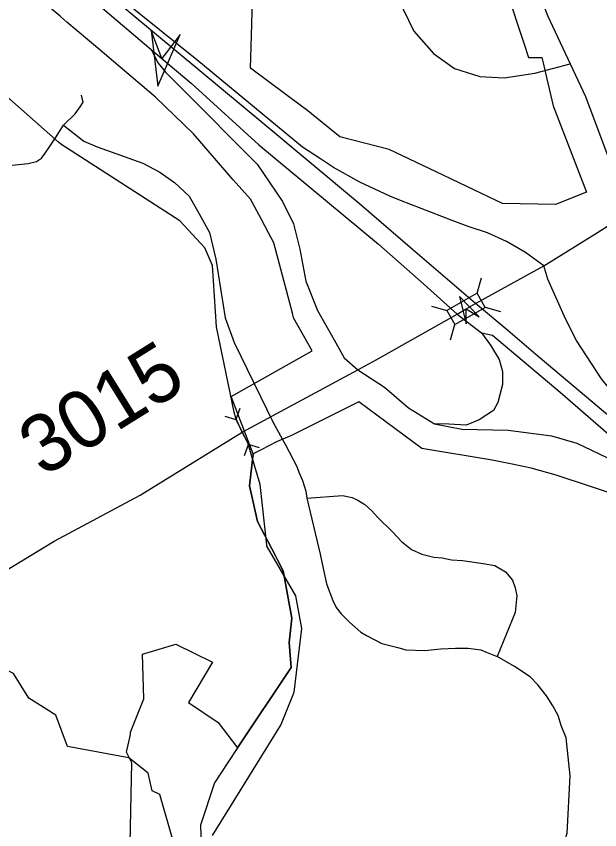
# Model space of a CAD drawing. Extents: x 2001466 to 31450019, y -30647475 to 847247.
# Drawn here: x 31439706 to 31442235, y -30624939 to -30621416 of the extents above; entities that cross this region are included whole.
import ezdxf

# ---------------------------------------------------------------- set-up
doc = ezdxf.new("R2010")
doc.units = 0
for name, color, linetype in [('Exist Boundary Political City Limit New', 7, 'Continuous'), ('Exist Hydrographic Creek Single Shore', 7, 'Continuous'), ('Exist Road Non-System Type 51', 7, 'Continuous'), ('Exist Road Primary Interstate Divided Center Attributed', 7, 'Continuous'), ('Exist Road Primary Interstate Ramp 1 Lane Attributed', 7, 'Continuous'), ('Exist Road Primary Interstate Structure Ovrhead Sign Attributed CELL', 7, 'Continuous'), ('Exist Road Secondary Structure Culvert CELL', 7, 'Continuous'), ('Exist Road Secondary Structure Standard Bridge Attributed CELL', 7, 'Continuous'), ('Exist Road Secondary Structure Standard Bridge CELL', 7, 'Continuous'), ('Exist Road Secondary Type 51 Attributed', 7, 'Continuous'), ('Exist Road Secondary Type 51 Number Label', 7, 'Continuous'), ('Map Preparation Boundary City Limit Buffer Line', 7, 'Continuous')]:
    doc.layers.add(name, color=color, linetype=linetype)

msp = doc.modelspace()

# ---------------------------------------------------------------- linework, layer by layer
at = {"layer": 'Exist Boundary Political City Limit New'}
for points in [[(31441833.9, -30621313.3), (31441905.3, -30621529), (31441926.8, -30621594.3), (31441983.8, -30621594.5), (31441989.4, -30621618.3), (31442004, -30621681.1), (31442033, -30621804.8), (31442177.8, -30622178.8), (31442042.9, -30622232.2), (31441814, -30622227.6), (31441691.6, -30622169.4), (31441525.9, -30622090.5), (31441321.9, -30621993.3), (31441108.8, -30621939), (31440961.9, -30621820), (31440948.3, -30621809.8), (31440720.8, -30621641.5), (31440723.5, -30621548.6), (31440735.3, -30621147.8)], [(31442352.3, -30623504.6), (31442046.3, -30623403.6), (31441938.3, -30623373.6), (31441854.9, -30623356.6), (31441768.4, -30623338.8), (31441463.8, -30623288.1), (31441191.6, -30623086.7), (31440898.5, -30623231.4), (31440834.5, -30623260), (31440767.8, -30623294.1), (31440732.9, -30623312)], [(31440732.9, -30623312), (31440716.4, -30623450.1), (31440751.9, -30623605.1), (31440829.4, -30623753.3), (31440838.1, -30623770.1), (31440863.1, -30623817.8), (31440900.4, -30624023.5), (31440888.8, -30624128.8), (31440897.3, -30624237.5), (31440664.3, -30624584.6)], [(31440664.3, -30624584.6), (31440622.6, -30624648.1), (31440564.8, -30624737), (31440504.1, -30624919.1), (31440518.3, -30625317.9), (31440493, -30625317.1), (31440483.9, -30625317), (31440193.6, -30625312.4)]]:
    msp.add_lwpolyline(points, dxfattribs=at)
at = {"layer": 'Exist Hydrographic Creek Single Shore'}
for p, q in [((31440791.7, -30623705.4), (31440763.8, -30623444.3)), ((31440907.2, -30624351.4), (31440909.5, -30624345.8))]:
    msp.add_line(p, q, dxfattribs=at)
for points in [[(31439888.4, -30621961.3), (31439539.5, -30621654.5), (31439388.3, -30621448), (31438996.5, -30621246.3), (31438888.4, -30621129.3), (31438779.3, -30620940), (31438746.5, -30620821.2), (31438753.5, -30620214.4), (31438794.3, -30620077.4)], [(31440763.8, -30623444.3), (31440709.3, -30623263.2), (31440685, -30623217.3), (31440658.4, -30623156.7), (31440651, -30623131.2), (31440574.4, -30622761.7), (31440557.3, -30622495.6), (31440523.5, -30622419.4), (31440415.4, -30622302.4), (31439898.5, -30621970.2), (31439888.4, -30621961.3)], [(31440512.4, -30625135.9), (31440412.4, -30625078), (31440328.5, -30624787.5), (31440294.5, -30624770.5), (31440277.4, -30624694.7), (31440194.4, -30624627.4), (31439927.4, -30624579.3), (31439877.4, -30624443.7), (31439760.5, -30624369.1), (31439693.5, -30624262.8), (31439260.4, -30624053.8), (31438998.6, -30623756.5), (31438963.5, -30623729.3), (31438939.7, -30623703.8), (31438905.2, -30623679.5), (31438856.5, -30623647.7), (31438567.5, -30623465.4), (31438475.4, -30623365.1)], [(31440805.3, -30623733.3), (31440792.3, -30623711.1), (31440791.7, -30623705.4)], [(31440909.5, -30624345.8), (31440910.4, -30624343.5), (31440943.4, -30624068.5), (31440918.4, -30623926.9), (31440805.3, -30623733.3)], [(31440556.4, -30624964.6), (31440852.4, -30624486.6), (31440907.2, -30624351.4)]]:
    msp.add_lwpolyline(points, dxfattribs=at)
at = {"layer": 'Exist Road Non-System Type 51'}
for p, q in [((31439875.5, -30621943), (31439911.2, -30621888)), ((31440820.9, -30623178.6), (31440872.6, -30623272.2))]:
    msp.add_line(p, q, dxfattribs=at)
for points in [[(31441344.4, -30621128.1), (31441361.8, -30621294.2), (31441383, -30621385), (31441429.3, -30621481.6), (31441514.3, -30621578.2), (31441605, -30621641.9), (31441715, -30621676.7), (31441821.2, -30621682.5), (31441954.4, -30621663.2), (31442107.5, -30621621.9)], [(31439911.2, -30621888), (31439960.7, -30621838.5), (31439982.7, -30621808.2), (31439996.5, -30621788.9), (31439988.2, -30621758.7)], [(31439911.2, -30621888), (31439998.7, -30621956.8), (31440056.4, -30621981.6), (31440254.4, -30622053.1), (31440328.6, -30622091.6), (31440391.9, -30622135.7), (31440455.1, -30622196.2), (31440490.9, -30622259.5), (31440543.1, -30622353.1), (31440570.6, -30622468.6), (31440611.9, -30622721.8), (31440650.4, -30622829.1), (31440820.9, -30623178.6)], [(31439688.5, -30622061.4), (31439757.3, -30622053.5), (31439793.1, -30622044.7), (31439815, -30622030.2), (31439831.5, -30622009.1), (31439850.7, -30621981.6), (31439875.5, -30621943)], [(31440872.6, -30623272.2), (31440922.1, -30623365.7), (31440930.3, -30623390.5), (31440946.8, -30623426.3), (31440960.6, -30623473), (31440966.1, -30623503.3)], [(31440966.1, -30623503.3), (31441120.1, -30623492.3), (31441161.3, -30623500.6), (31441186.1, -30623511.6), (31441216.3, -30623530.8), (31441246.6, -30623558.3), (31441271.3, -30623585.9), (31441337.3, -30623649.1), (31441375.8, -30623690.4), (31441419.8, -30623726.2), (31441463.8, -30623745.5), (31441516, -30623759.2), (31441551.8, -30623762), (31441593, -30623770.2), (31441639.8, -30623773), (31441730.5, -30623786.7), (31441780, -30623795), (31441826.8, -30623822.5), (31441857, -30623858.3), (31441868, -30623891.3), (31441876.3, -30623927.1), (31441868, -30623998.6), (31441791, -30624188.5)], [(31440966.1, -30623503.3), (31441023.8, -30623745.5), (31441050.8, -30623874.8), (31441078.3, -30623946.3), (31441092, -30623976.6), (31441114, -30624004.1), (31441149.8, -30624039.9), (31441199.3, -30624083.9), (31441224, -30624097.7), (31441259.8, -30624117), (31441290, -30624133.5), (31441325.8, -30624141.7), (31441359.3, -30624150), (31441395, -30624161), (31441477.5, -30624163.7), (31441546.3, -30624155.5), (31441609.5, -30624152.7), (31441664.5, -30624152.7), (31441719.5, -30624161), (31441747, -30624172), (31441791, -30624188.5)], [(31441646.7, -30627115.6), (31441742.3, -30627044.7), (31441976.6, -30626829.8), (31442132.8, -30626673.5), (31442152.3, -30626399.9), (31442113.3, -30625970.1), (31442015.7, -30625423), (31441996.1, -30625266.7), (31442093.8, -30624954.1), (31442106.7, -30624705.8), (31442090.2, -30624540.7), (31442068.2, -30624488.4), (31442054.5, -30624444.4), (31442032.5, -30624403.1), (31442005, -30624359.1), (31441966.5, -30624312.3), (31441933.5, -30624276.6), (31441865.3, -30624232.5), (31441791, -30624188.5)]]:
    msp.add_lwpolyline(points, dxfattribs=at)
at = {"layer": 'Exist Road Primary Interstate Divided Center Attributed'}
for points in [[(31438048.9, -30619684.1), (31438111.1, -30619738.8), (31438627.8, -30620173.3), (31438916.5, -30620414.6), (31439590.6, -30620971.6), (31439878.6, -30621209.9), (31440291.2, -30621559.8)], [(31441697.1, -30622660.9), (31441423.5, -30622426.6), (31441193.4, -30622228.5), (31440775, -30621879.5), (31440032.5, -30621260.9)], [(31440291.2, -30621559.8), (31440337.5, -30621598.9), (31440464.4, -30621706.8), (31440757.3, -30621972.5), (31441275.5, -30622403.3), (31441473.2, -30622576.6), (31441616.7, -30622706)], [(31442906.5, -30623678.1), (31442625.9, -30623443.3), (31442279, -30623151), (31441958.6, -30622881.2), (31441836.5, -30622777.1), (31441697.1, -30622660.9)], [(31441616.7, -30622706), (31441722.9, -30622788.1)], [(31441722.9, -30622788.1), (31441770.5, -30622798), (31442064, -30623044.1), (31442448.1, -30623377.7), (31442660.8, -30623560.6)]]:
    msp.add_lwpolyline(points, dxfattribs=at)
at = {"layer": 'Exist Road Primary Interstate Ramp 1 Lane Attributed'}
for points in [[(31441992.1, -30622496.5), (31441913.3, -30622438.8), (31441831, -30622392.5), (31441748.2, -30622353.9), (31441664.6, -30622326.3), (31441595.9, -30622300.9), (31441371.4, -30622214.6), (31441325.2, -30622194.8), (31441195.9, -30622135.4), (31441080.8, -30622071.1), (31441025.1, -30622033.8), (31440947.2, -30621983.1), (31440488.2, -30621604.8), (31440172.1, -30621350.9), (31440032.5, -30621260.9)], [(31440291.2, -30621559.8), (31440320.9, -30621618.9), (31440354.2, -30621660.1), (31440425.1, -30621730.4), (31440750.9, -30622056.8), (31440859.6, -30622219.3), (31440907.6, -30622315.1), (31440935, -30622425.6), (31440961.1, -30622563.7), (31441011.5, -30622690.4), (31441083.7, -30622817.1), (31441127.6, -30622895.1), (31441186.6, -30622947.1)], [(31442906.5, -30623678.1), (31442875.3, -30623619.2), (31442799.4, -30623541.6), (31442416.6, -30623174), (31442353.7, -30623113.4), (31442303.8, -30623061.3), (31442242.6, -30622987), (31442133.8, -30622820.8), (31442086.2, -30622727), (31442010.6, -30622554.7), (31441992.1, -30622496.5)], [(31441722.9, -30622788.1), (31441762.2, -30622841.1), (31441799.3, -30622903), (31441813.3, -30622955.1), (31441813.3, -30623010.6), (31441792.8, -30623088.8), (31441774.3, -30623123.5), (31441712.4, -30623163.7), (31441656, -30623187.6), (31441581, -30623183.3), (31441519.4, -30623181.9)], [(31441186.6, -30622947.1), (31441302.3, -30623023.3), (31441406.7, -30623112.4), (31441519.4, -30623181.9)], [(31441519.4, -30623181.9), (31441636.7, -30623204.7), (31441838.5, -30623208.6), (31442026.1, -30623233), (31442136.4, -30623265.4), (31442295.6, -30623341.8), (31442451.4, -30623439.3), (31442488, -30623456.2), (31442597.7, -30623546.3), (31442845.3, -30623742.4), (31443123.5, -30623974.7), (31443241.2, -30624040.3)]]:
    msp.add_lwpolyline(points, dxfattribs=at)
at = {"layer": 'Exist Road Primary Interstate Structure Ovrhead Sign Attributed CELL'}
msp.add_lwpolyline([(31440337.5, -30621598.9), (31440291.2, -30621477.5), (31440320.1, -30621719.6), (31440416.1, -30621495.5), (31440337.5, -30621598.9)], dxfattribs=at)
at = {"layer": 'Exist Road Secondary Structure Culvert CELL'}
for p, q in [((31440675.3, -30623115.5), (31440657.9, -30623163.2)), ((31440609.4, -30623148.4), (31440657.9, -30623163.2)), ((31440657.9, -30623163.2), (31440712, -30623271.4)), ((31440694.6, -30623319.1), (31440712, -30623271.4)), ((31440760.6, -30623286.1), (31440712, -30623271.4))]:
    msp.add_line(p, q, dxfattribs=at)
at = {"layer": 'Exist Road Secondary Structure Standard Bridge Attributed CELL'}
msp.add_lwpolyline([(31441656.8, -30622683.7), (31441712, -30622718.1), (31441627.3, -30622630.4), (31441656.8, -30622748.7), (31441656.8, -30622683.7)], dxfattribs=at)
at = {"layer": 'Exist Road Secondary Structure Standard Bridge CELL'}
for p, q in [((31441704.2, -30622615.8), (31441722.7, -30622549.4)), ((31441506.1, -30622671.5), (31441572.6, -30622690)), ((31441738.2, -30622675.9), (31441804.7, -30622694.3)), ((31441588.9, -30622817.9), (31441607.3, -30622751.4))]:
    msp.add_line(p, q, dxfattribs=at)
msp.add_lwpolyline([(31441607.3, -30622751.4), (31441738.8, -30622677), (31441704.1, -30622615.6), (31441572.6, -30622690), (31441607.3, -30622751.4)], dxfattribs=at)
at = {"layer": 'Exist Road Secondary Type 51 Attributed'}
for points in [[(31442364.4, -30622265.3), (31442271, -30622024.3), (31442174.5, -30621765), (31442010.3, -30621413.9), (31441878.3, -30621069.3), (31441723, -30620681.1), (31441586.2, -30620323.6), (31441544.4, -30620159.3), (31441513, -30619987)], [(31441992.1, -30622496.5), (31442226, -30622352.9), (31442364.4, -30622265.3)], [(31441697.1, -30622660.9), (31441992.1, -30622496.5)], [(31441616.7, -30622706), (31441656.8, -30622683.7), (31441697.1, -30622660.9)], [(31441186.6, -30622947.1), (31441265.6, -30622904.6), (31441616.7, -30622706)], [(31438951.3, -30624488.5), (31439092.9, -30624298.4), (31439308.6, -30624072.2), (31439514.6, -30623904.7), (31439870.3, -30623689.7), (31440243.6, -30623490), (31440685, -30623217.3), (31441186.6, -30622947.1)]]:
    msp.add_lwpolyline(points, dxfattribs=at)
at = {"layer": 'Map Preparation Boundary City Limit Buffer Line'}
for points in [[(31441833.9, -30621313.3), (31441905.3, -30621529), (31441926.8, -30621594.3), (31441983.8, -30621594.5), (31441989.4, -30621618.3), (31442004, -30621681.1), (31442033, -30621804.8), (31442177.8, -30622178.8), (31442042.9, -30622232.2), (31441814, -30622227.6), (31441691.6, -30622169.4), (31441525.9, -30622090.5), (31441321.9, -30621993.3), (31441108.8, -30621939), (31440961.9, -30621820), (31440948.3, -30621809.8), (31440720.8, -30621641.5), (31440723.5, -30621548.6), (31440735.3, -30621147.8)], [(31440732.9, -30623312), (31440636.9, -30623063.6), (31440989, -30622865.6), (31440908.3, -30622722.7), (31440903, -30622702.5), (31440890.4, -30622653), (31440822, -30622397.2), (31440799.5, -30622354.8), (31440767.6, -30622294.3), (31440722, -30622208), (31440646.6, -30622125.2), (31440474, -30621926.1), (31440309.8, -30621766.6), (31440299.5, -30621758), (31440156.6, -30621636.7), (31440060.3, -30621555), (31439925.8, -30621441.2), (31439899.5, -30621419), (31439896.6, -30621416.6), (31439790.8, -30621327)], [(31442352.3, -30623504.6), (31442046.3, -30623403.6), (31441938.3, -30623373.6), (31441854.9, -30623356.6), (31441768.4, -30623338.8), (31441463.8, -30623288.1), (31441191.6, -30623086.7), (31440898.5, -30623231.4), (31440834.5, -30623260), (31440767.8, -30623294.1), (31440732.9, -30623312)], [(31440664.3, -30624584.6), (31440897.3, -30624237.5), (31440888.8, -30624128.8), (31440900.4, -30624023.5), (31440863.1, -30623817.8), (31440838.1, -30623770.1), (31440829.4, -30623753.3), (31440751.9, -30623605.1), (31440716.4, -30623450.1), (31440732.9, -30623312)], [(31440732.9, -30623312), (31440716.4, -30623450.1), (31440751.9, -30623605.1), (31440829.4, -30623753.3), (31440838.1, -30623770.1), (31440863.1, -30623817.8), (31440900.4, -30624023.5), (31440888.8, -30624128.8), (31440897.3, -30624237.5), (31440664.3, -30624584.6)], [(31440193.6, -30625312.4), (31440195.8, -30625208.1), (31440207.3, -30624650.4), (31440183.4, -30624603.1), (31440201.1, -30624527), (31440201.1, -30624516.7), (31440258.8, -30624371.8), (31440252.5, -30624178.8), (31440398.1, -30624135.5), (31440556, -30624213.5), (31440452.1, -30624388.1), (31440581.5, -30624475.5), (31440664.3, -30624584.6)], [(31440664.3, -30624584.6), (31440622.6, -30624648.1), (31440564.8, -30624737), (31440504.1, -30624919.1), (31440518.3, -30625317.9), (31440493, -30625317.1), (31440483.9, -30625317), (31440193.6, -30625312.4)]]:
    msp.add_lwpolyline(points, dxfattribs=at)

# ---------------------------------------------------------------- texts
at = {"layer": 'Exist Road Secondary Type 51 Number Label'}
msp.add_text('3015', height=250, rotation=31.918, dxfattribs=at).set_placement((31439822.6, -30623415.1))

doc.saveas('drawing.dxf')
